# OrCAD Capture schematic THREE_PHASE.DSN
size A
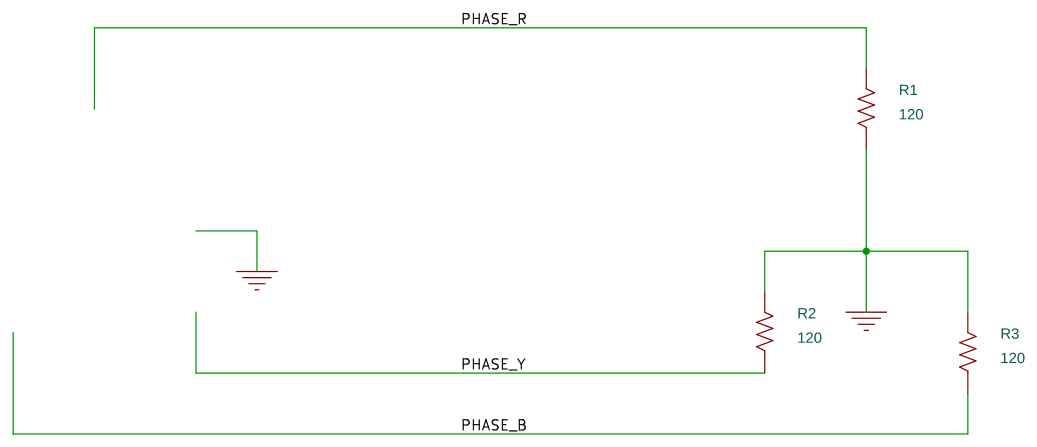
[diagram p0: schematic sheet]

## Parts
R1  120  [AXRC05]
R2  120  [AXRC05]
R3  120  [AXRC05]

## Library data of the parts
R1-R3 = R

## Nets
0: R1.1 R2.2 R3.2
PHASE_B: R3.1
PHASE_R: R1.2
PHASE_Y: R2.1
